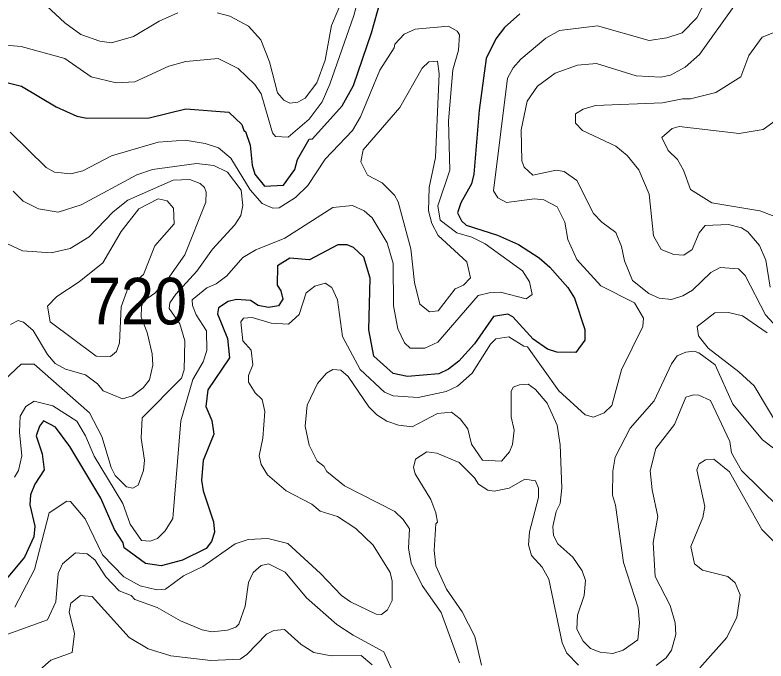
# Model space of a CAD drawing. Extents: x 763.2 to 816.8, y 7896.5 to 7952.7.
# Drawn here: x 775.277 to 777.852, y 7898.239 to 7900.455 of the extents above; entities that cross this region are included whole.
import ezdxf

# ---------------------------------------------------------------- set-up
doc = ezdxf.new("R2010")
doc.units = 0
doc.header["$LTSCALE"] = 0.064
doc.layers.add('1', color=7, linetype='Continuous', lineweight=25)
doc.layers.add('2', color=7, linetype='Continuous', lineweight=13)
doc.layers.add('21', color=7, linetype='Continuous')

msp = doc.modelspace()

# ---------------------------------------------------------------- linework, layer by layer
at = {"layer": '1'}
for points in [[(775.2301, 7900.2279), (775.2989, 7900.211), (775.4186, 7900.1394), (775.4885, 7900.1076), (775.5237, 7900.101), (775.7373, 7900.1018), (775.8624, 7900.1333), (776.0101, 7900.1218), (776.055, 7900.0789), (776.0611, 7900.0588), (776.0675, 7900.0556), (776.0838, 7900.0082), (776.0896, 7899.9396), (776.0991, 7899.9085), (776.1319, 7899.8674), (776.1976, 7899.8714), (776.236, 7899.9249), (776.246, 7899.9593), (776.2859, 7900.029), (776.2974, 7900.0304), (776.3984, 7900.1436), (776.4371, 7900.2135), (776.4996, 7900.3941), (776.5296, 7900.5033)], [(777.0079, 7900.4589), (776.9557, 7900.4118), (776.9257, 7900.3735), (776.8926, 7900.3054), (776.8685, 7900.1284), (776.8501, 7899.9092), (776.8417, 7899.8757), (776.806, 7899.8105), (776.7942, 7899.7766), (776.8076, 7899.7486), (776.8239, 7899.7343), (776.9315, 7899.7), (777.0038, 7899.6672), (777.0737, 7899.6219), (777.1109, 7899.5899), (777.1721, 7899.5205), (777.1954, 7899.4837), (777.231, 7899.3766), (777.2307, 7899.3391), (777.1998, 7899.2974), (777.1345, 7899.2984), (777.1025, 7899.309), (777.053, 7899.343), (776.9834, 7899.4193), (776.9666, 7899.4282), (776.9179, 7899.4204), (776.8528, 7899.3275), (776.7984, 7899.267), (776.7629, 7899.2396), (776.73, 7899.2244), (776.6225, 7899.215), (776.5739, 7899.2249), (776.5075, 7899.2849), (776.4902, 7899.3752), (776.495, 7899.5527), (776.4725, 7899.624), (776.437, 7899.6571), (776.4161, 7899.6666), (776.3834, 7899.6666), (776.2863, 7899.6149), (776.219, 7899.6205), (776.1769, 7899.5947), (776.1762, 7899.5281), (776.1886, 7899.5086), (776.1956, 7899.4802), (776.1809, 7899.4571), (776.1459, 7899.4517), (776.1107, 7899.4582), (776.0847, 7899.4752), (776.0366, 7899.4795), (776.008, 7899.4724), (775.9742, 7899.4506), (775.9712, 7899.4296), (776.0053, 7899.3456), (776.0118, 7899.279), (775.9381, 7899.1688), (775.9317, 7899.1124), (775.9523, 7899.0644), (775.9592, 7899.0172), (775.922, 7898.9272), (775.9166, 7898.8599), (775.9218, 7898.823), (775.9572, 7898.7169), (775.9607, 7898.6808), (775.9505, 7898.6494), (775.9323, 7898.6247), (775.8508, 7898.5855), (775.7785, 7898.5659), (775.7249, 7898.5739), (775.6509, 7898.6278), (775.6481, 7898.6449), (775.6183, 7898.6905), (775.5714, 7898.7974), (775.4647, 7898.9754), (775.4159, 7899.0415), (775.375, 7899.063), (775.3608, 7899.045), (775.3497, 7899.011), (775.3697, 7898.9502), (775.3772, 7898.8944)], [(775.3772, 7898.8944), (775.3444, 7898.846), (775.3298, 7898.8089), (775.3283, 7898.7744), (775.3446, 7898.7016), (775.341, 7898.6652)], [(775.341, 7898.6652), (775.3092, 7898.5952), (775.218, 7898.4869)]]:
    msp.add_lwpolyline(points, dxfattribs=at)
at = {"layer": '2'}
for points in [[(776.4204, 7900.5571), (776.3625, 7900.4192), (776.3406, 7900.3002), (776.3114, 7900.222), (776.2719, 7900.1693), (776.2471, 7900.1563), (776.2188, 7900.1519), (776.1981, 7900.1627), (776.1767, 7900.1881), (776.1495, 7900.2943), (776.1194, 7900.3697), (776.077, 7900.4166), (776.0134, 7900.4507), (775.9698, 7900.462)], [(775.1804, 7900.3572), (775.2979, 7900.3472), (775.448, 7900.3053), (775.5379, 7900.2426), (775.6233, 7900.2223), (775.688, 7900.2261), (775.8049, 7900.2798), (775.8623, 7900.2958), (775.9739, 7900.3059), (776.042, 7900.2711), (776.0993, 7900.217), (776.1205, 7900.185), (776.1596, 7900.0507), (776.1696, 7900.0381), (776.2134, 7900.0358), (776.2851, 7900.0979), (776.3298, 7900.1565), (776.3569, 7900.2174), (776.4388, 7900.4533), (776.4622, 7900.5427)], [(777.6619, 7900.5362), (777.6146, 7900.4448), (777.5641, 7900.3938), (777.5115, 7900.3769), (777.4517, 7900.3672), (777.2747, 7900.4176), (777.1441, 7900.4012), (777.0973, 7900.3754), (777.0117, 7900.3033), (776.9848, 7900.2732), (776.9653, 7900.2384), (776.9175, 7899.852), (776.9324, 7899.828), (776.9618, 7899.8117), (777.0579, 7899.8244), (777.0906, 7899.8208), (777.1357, 7899.7965), (777.1619, 7899.7447), (777.1725, 7899.6843), (777.2035, 7899.6163), (777.2852, 7899.5262), (777.4015, 7899.4682), (777.4315, 7899.4147), (777.4301, 7899.3867), (777.3563, 7899.2379), (777.3231, 7899.1152), (777.2974, 7899.0903), (777.2602, 7899.0755), (777.2322, 7899.0832), (777.1417, 7899.1662), (777.0338, 7899.3163), (777.0211, 7899.3186), (776.9704, 7899.3512), (776.9254, 7899.3439), (776.9076, 7899.3259), (776.8444, 7899.2263), (776.794, 7899.1823), (776.7547, 7899.164), (776.6594, 7899.1426), (776.5734, 7899.1488), (776.5437, 7899.161), (776.4604, 7899.2387), (776.4002, 7899.3523), (776.3831, 7899.4778), (776.3633, 7899.5204), (776.34, 7899.5349), (776.3046, 7899.5252), (776.2749, 7899.5016), (776.2513, 7899.4275), (776.2143, 7899.3946), (776.1558, 7899.3975), (776.09, 7899.4169), (776.0608, 7899.4146), (776.0514, 7899.4023), (776.0578, 7899.3373), (776.0871, 7899.3051), (776.0922, 7899.2551), (776.078, 7899.2183), (776.0778, 7899.196), (776.1009, 7899.1591), (776.1249, 7899.1359), (776.1331, 7899.0949), (776.1271, 7899.0029), (776.1138, 7898.9428), (776.1204, 7898.9133), (776.1424, 7898.8775), (776.2072, 7898.8228), (776.2944, 7898.7776), (776.3236, 7898.7536), (776.3826, 7898.7351), (776.445, 7898.6934), (776.5044, 7898.6369), (776.5632, 7898.5425), (776.5703, 7898.5131), (776.5705, 7898.4466), (776.5539, 7898.4142), (776.5332, 7898.3989), (776.5154, 7898.3997), (776.4275, 7898.4416), (776.3967, 7898.4635), (776.3241, 7898.5394), (776.2121, 7898.6418), (776.1433, 7898.6592), (776.0769, 7898.6559), (776.0319, 7898.6414), (775.9204, 7898.5629), (775.8548, 7898.5314), (775.7924, 7898.4852), (775.7637, 7898.4838)], [(775.8357, 7900.4619), (775.7713, 7900.434), (775.6831, 7900.3814), (775.6082, 7900.359), (775.5681, 7900.3653), (775.5031, 7900.388), (775.4482, 7900.4278), (775.3845, 7900.4864)], [(777.8761, 7899.3982), (777.8501, 7899.4265), (777.7801, 7899.5616), (777.758, 7899.5846), (777.6949, 7899.5893), (777.6629, 7899.5715), (777.6001, 7899.5114), (777.5669, 7899.492), (777.5279, 7899.4788), (777.4858, 7899.4839), (777.4503, 7899.5), (777.3947, 7899.5447), (777.3663, 7899.612), (777.3563, 7899.6613), (777.3373, 7899.7091), (777.2889, 7899.7441), (777.2605, 7899.7742), (777.2028, 7899.8874), (777.1598, 7899.9181), (777.1327, 7899.923), (777.0529, 7899.9055), (777.0226, 7899.9332), (777.0145, 7899.9551), (777.0128, 7900.0611), (777.0334, 7900.1594), (777.0686, 7900.2108), (777.1295, 7900.2552), (777.2051, 7900.283), (777.2702, 7900.2881), (777.4065, 7900.2467), (777.4916, 7900.2421), (777.5243, 7900.2488), (777.575, 7900.2762), (777.6235, 7900.3189), (777.7412, 7900.4841)], [(776.5011, 7899.7591), (776.5533, 7899.6732), (776.5738, 7899.602), (776.5744, 7899.4569), (776.5891, 7899.3781), (776.6127, 7899.3302), (776.6321, 7899.3124), (776.6824, 7899.3119), (776.7267, 7899.3332), (776.8652, 7899.4926), (776.9026, 7899.5023), (776.9413, 7899.504), (777.0293, 7899.4813), (777.0503, 7899.4958), (777.0409, 7899.5395), (777.0172, 7899.5777), (776.8888, 7899.6704), (776.8431, 7899.6926), (776.7923, 7899.7073), (776.735, 7899.7513), (776.727, 7899.8005), (776.7678, 7899.9222), (776.7629, 7900.0922), (776.7778, 7900.2666), (776.7971, 7900.3343), (776.8007, 7900.3873), (776.793, 7900.3989), (776.7636, 7900.4162), (776.6489, 7900.4061), (776.6118, 7900.3887), (776.5791, 7900.355), (776.5767, 7900.3421), (776.5273, 7900.2652), (776.4621, 7900.1056), (776.4337, 7900.0591), (776.3403, 7899.9602), (776.2812, 7899.8704), (776.239, 7899.8286), (776.1823, 7899.7934), (776.1614, 7899.7922), (776.1239, 7899.8083), (776.0832, 7899.8555), (776.0173, 7899.9638), (775.9748, 7899.999), (775.929, 7900.0136), (775.8606, 7900.025), (775.768, 7900.0183), (775.6077, 7899.9723), (775.5096, 7899.9203), (775.4688, 7899.9102), (775.4126, 7899.9162), (775.3833, 7899.9315), (775.2608, 7900.053)], [(777.8822, 7900.3963), (777.8389, 7900.3793), (777.7935, 7900.316), (777.766, 7900.2429), (777.6804, 7900.189), (777.5933, 7900.1672), (777.5651, 7900.1677), (777.4968, 7900.1533), (777.2668, 7900.1448), (777.2254, 7900.1321), (777.1991, 7900.1154), (777.1989, 7900.084), (777.2227, 7900.0586), (777.3371, 7900.0049), (777.3759, 7899.9725), (777.4161, 7899.9235), (777.4513, 7899.8401), (777.4658, 7899.697), (777.4928, 7899.6507), (777.536, 7899.6335), (777.5706, 7899.6313), (777.599, 7899.6507), (777.6225, 7899.7079), (777.6437, 7899.7325), (777.7236, 7899.7358), (777.7681, 7899.7254), (777.7901, 7899.711), (777.8298, 7899.6644), (777.8508, 7899.6137), (777.8659, 7899.5216)], [(777.8823, 7899.7635), (777.8302, 7899.7833), (777.6666, 7899.811), (777.5926, 7899.8564), (777.569, 7899.9229), (777.5483, 7899.9591), (777.5168, 7899.9896), (777.4948, 7900.0352), (777.5304, 7900.066), (777.5542, 7900.0727), (777.7598, 7900.0481), (777.8419, 7900.0627), (777.8882, 7900.0953)], [(775.2708, 7899.8505), (775.305, 7899.8165), (775.3579, 7899.7901), (775.4249, 7899.7788), (775.5034, 7899.8032), (775.6943, 7899.9072), (775.7478, 7899.9255), (775.8987, 7899.946), (775.9587, 7899.9381), (776.0056, 7899.9161), (776.052, 7899.8544), (776.0576, 7899.8018), (776.0512, 7899.7671), (776.0308, 7899.7354), (775.9544, 7899.652), (775.9001, 7899.5765), (775.8279, 7899.4975), (775.8082, 7899.4679), (775.8051, 7899.4485), (775.8423, 7899.3958), (775.8588, 7899.3372), (775.857, 7899.2375), (775.8476, 7899.2088), (775.713, 7899.0727), (775.7095, 7899.0038), (775.7208, 7898.9284), (775.7174, 7898.8921), (775.6992, 7898.8419), (775.6809, 7898.8323), (775.6591, 7898.8368), (775.62, 7898.875), (775.6061, 7898.9027), (775.5747, 7899.0088), (775.5319, 7899.0899), (775.3422, 7899.2567), (775.298, 7899.2576), (775.22, 7899.1852)], [(775.2617, 7899.3931), (775.2883, 7899.407), (775.3061, 7899.4015), (775.3393, 7899.3729), (775.3878, 7899.2899), (775.4149, 7899.2599), (775.4502, 7899.24), (775.519, 7899.2207), (775.5601, 7899.1898), (775.5797, 7899.1663), (775.6458, 7899.138), (775.6801, 7899.1484), (775.7169, 7899.1765), (775.7376, 7899.2037), (775.7493, 7899.2544), (775.7476, 7899.2927), (775.7296, 7899.3656), (775.7099, 7899.419), (775.7101, 7899.4553), (775.719, 7899.474), (775.7567, 7899.5003), (775.7999, 7899.5471), (775.8597, 7899.6321), (775.9312, 7899.8132), (775.9328, 7899.8468), (775.9264, 7899.8632), (775.9121, 7899.8767), (775.8764, 7899.8903), (775.8187, 7899.8886), (775.6635, 7899.8196), (775.6136, 7899.7798), (775.5308, 7899.694), (775.4661, 7899.6539), (775.4005, 7899.6389), (775.3021, 7899.6464), (775.1968, 7899.6948)], [(776.1027, 7899.6496), (776.2025, 7899.6899), (776.3668, 7899.7949), (776.4339, 7899.8014), (776.4746, 7899.7837), (776.5011, 7899.7591)], [(775.2755, 7898.8701), (775.2887, 7898.8928), (775.3002, 7898.9427), (775.2921, 7899.0236), (775.2946, 7899.0785), (775.3139, 7899.1119), (775.3432, 7899.1308), (775.4071, 7899.1146), (775.489, 7899.0619), (775.5184, 7899.0118), (775.5488, 7898.9414), (775.6462, 7898.7791), (775.6717, 7898.7088), (775.7107, 7898.6527), (775.74, 7898.6497), (775.7659, 7898.6592), (775.7914, 7898.686), (775.818, 7898.7282), (775.8458, 7899.063), (775.887, 7899.205), (775.922, 7899.2656), (775.9346, 7899.3043), (775.9331, 7899.3715), (775.8978, 7899.4267), (775.8851, 7899.4585), (775.8842, 7899.4781), (775.9349, 7899.5187), (775.967, 7899.5323), (776.0034, 7899.56), (776.0585, 7899.6228), (776.1027, 7899.6496)], [(777.8954, 7899.0407), (777.8109, 7899.1824), (777.7586, 7899.2312), (777.6537, 7899.3119), (777.6199, 7899.355), (777.6161, 7899.3866), (777.676, 7899.4333), (777.7237, 7899.435), (777.7715, 7899.4226), (777.8557, 7899.3644)], [(776.5798, 7898.7517), (776.407, 7898.8398), (776.3457, 7898.8896), (776.3354, 7898.9072), (776.3127, 7898.9244), (776.2859, 7898.9796), (776.2716, 7899.0446), (776.2792, 7899.1164), (776.3139, 7899.1912), (776.3455, 7899.2262), (776.3663, 7899.239), (776.3941, 7899.2362), (776.4194, 7899.2148), (776.4905, 7899.111), (776.5176, 7899.084), (776.5516, 7899.0618), (776.5917, 7899.0486), (776.6385, 7899.0424), (776.7258, 7899.0885), (776.7735, 7899.0921), (776.8037, 7899.0701), (776.8299, 7899.0355), (776.8416, 7898.9826), (776.8798, 7898.9275), (776.9455, 7898.9245), (776.9727, 7898.9562), (776.9824, 7898.9813), (776.9881, 7899.0314), (776.9783, 7899.0769), (776.9784, 7899.164), (776.9848, 7899.178), (777.0067, 7899.1866), (777.0361, 7899.1885), (777.062, 7899.1704), (777.1021, 7899.124), (777.1357, 7899.0479), (777.146, 7898.9802), (777.1524, 7898.8336), (777.1459, 7898.7792), (777.1325, 7898.7517), (777.1215, 7898.7002), (777.123, 7898.6699), (777.138, 7898.6414), (777.1899, 7898.595), (777.221, 7898.5482), (777.2327, 7898.5154), (777.2285, 7898.4644), (777.2052, 7898.3964), (777.2035, 7898.3479), (777.2252, 7898.3072), (777.2497, 7898.2824), (777.2836, 7898.269), (777.3266, 7898.265), (777.3625, 7898.2765), (777.4127, 7898.3119), (777.4187, 7898.3703), (777.4138, 7898.4221), (777.3629, 7898.5766), (777.3364, 7898.7738), (777.325, 7898.808), (777.3267, 7898.8901), (777.3348, 7898.9382), (777.3858, 7899.0374), (777.4683, 7899.1317), (777.5276, 7899.2582), (777.5475, 7899.2862), (777.5765, 7899.2986), (777.6058, 7899.3017), (777.6214, 7899.2963), (777.6778, 7899.2545), (777.7379, 7899.1205), (777.8396, 7898.9978), (777.9443, 7898.9189)], [(777.6611, 7899.1329), (777.6217, 7899.1507), (777.6035, 7899.1523), (777.5774, 7899.1444), (777.5382, 7899.05), (777.4744, 7898.9677)], [(777.8953, 7898.7663), (777.7676, 7898.8924), (777.7341, 7898.9526), (777.7274, 7898.9917), (777.6611, 7899.1329)], [(777.209, 7898.2252), (777.1694, 7898.2663), (777.1528, 7898.3014), (777.1068, 7898.5199), (777.0846, 7898.5614), (777.0476, 7898.6016), (777.0381, 7898.638), (777.0407, 7898.6824), (777.0716, 7898.8001), (777.0719, 7898.8325), (777.061, 7898.8572), (777.025, 7898.863), (776.9707, 7898.8317), (776.9197, 7898.8222), (776.8976, 7898.8252), (776.8658, 7898.846), (776.8524, 7898.8673), (776.7994, 7898.9198), (776.7232, 7898.9515), (776.6895, 7898.9564), (776.6506, 7898.9312), (776.643, 7898.9033), (776.6489, 7898.8806), (776.7028, 7898.7928), (776.7203, 7898.7474), (776.7251, 7898.7149), (776.7202, 7898.7092), (776.7136, 7898.6183), (776.7199, 7898.5654), (776.7561, 7898.486), (776.8105, 7898.4079), (776.8535, 7898.3235), (776.8763, 7898.2248)], [(777.4744, 7898.9677), (777.4549, 7898.8909), (777.4615, 7898.8263), (777.481, 7898.735), (777.4647, 7898.6455), (777.4713, 7898.5287), (777.5235, 7898.4299), (777.5401, 7898.3701), (777.5432, 7898.3301), (777.5284, 7898.2761), (777.5095, 7898.2495), (777.4751, 7898.2242)], [(777.6252, 7898.2152), (777.7173, 7898.3203), (777.752, 7898.3892), (777.7637, 7898.4666), (777.7463, 7898.5068), (777.7208, 7898.5293), (777.634, 7898.5509), (777.6067, 7898.5719), (777.5946, 7898.6324), (777.6352, 7898.7313), (777.642, 7898.7696), (777.6143, 7898.8948), (777.6223, 7898.9151), (777.6443, 7898.9294), (777.6726, 7898.932), (777.7269, 7898.8884), (777.8377, 7898.69), (777.8809, 7898.6466)], [(775.4673, 7898.7865), (775.4542, 7898.7876), (775.3936, 7898.7469), (775.3435, 7898.5525), (775.2765, 7898.4239)], [(775.7637, 7898.4838), (775.7063, 7898.4967), (775.6504, 7898.528), (775.5766, 7898.6032), (775.5179, 7898.7265), (775.4673, 7898.7865)], [(776.6726, 7898.4984), (776.6356, 7898.575), (776.6266, 7898.6259), (776.6295, 7898.6925), (776.6083, 7898.725), (776.5798, 7898.7517)], [(775.1854, 7898.307), (775.3882, 7898.3799), (775.4169, 7898.4425), (775.4244, 7898.5393), (775.4398, 7898.5723), (775.484, 7898.6107), (775.524, 7898.6071), (775.5511, 7898.5858), (775.588, 7898.5278), (775.6339, 7898.4794), (775.6747, 7898.4636), (775.6882, 7898.45), (775.7647, 7898.4229), (775.8442, 7898.3768), (775.9192, 7898.3457), (775.9521, 7898.3391), (776.0051, 7898.3447), (776.0336, 7898.3548), (776.0447, 7898.3658), (776.0665, 7898.4277), (776.0779, 7898.5082), (776.0935, 7898.543), (776.1204, 7898.5672), (776.1466, 7898.5721), (776.2029, 7898.5439), (776.2765, 7898.4557), (776.3805, 7898.3646), (776.436, 7898.3275), (776.5412, 7898.2707), (776.5716, 7898.2047)], [(776.8012, 7898.2333), (776.7383, 7898.4056), (776.6726, 7898.4984)], [(776.5016, 7898.226), (776.4638, 7898.2585), (776.3604, 7898.2568), (776.3018, 7898.2681), (776.2586, 7898.2953), (776.2006, 7898.3469), (776.1647, 7898.3435), (776.1391, 7898.3316), (776.0721, 7898.2611), (776.0489, 7898.2457), (775.948, 7898.2404), (775.8113, 7898.2568), (775.7339, 7898.2809), (775.668, 7898.3201), (775.5417, 7898.4603), (775.5013, 7898.4637), (775.468, 7898.4372), (775.463, 7898.4075), (775.481, 7898.334), (775.4727, 7898.2688), (775.4, 7898.2415), (775.3334, 7898.1843)]]:
    msp.add_lwpolyline(points, dxfattribs=at)
for points in [[(776.4623, 7899.9518), (776.4708, 7899.9921), (776.5967, 7900.1373), (776.6724, 7900.2727), (776.6963, 7900.2947), (776.725, 7900.2969), (776.7316, 7900.2528), (776.7183, 7899.9661), (776.6969, 7899.8633), (776.6944, 7899.783), (776.706, 7899.7393), (776.7277, 7899.6983), (776.8265, 7899.6079), (776.839, 7899.5536), (776.8144, 7899.5278), (776.7865, 7899.516), (776.7282, 7899.4403), (776.6979, 7899.4369), (776.6654, 7899.4636), (776.6462, 7899.5377), (776.6345, 7899.6527), (776.5911, 7899.8145), (776.5784, 7899.8365), (776.5357, 7899.8792), (776.4853, 7899.9054)], [(775.8226, 7899.7383), (775.8199, 7899.7919), (775.799, 7899.8172), (775.7682, 7899.8242), (775.7019, 7899.7901), (775.6414, 7899.7126), (775.5785, 7899.6049), (775.4964, 7899.5391), (775.4203, 7899.4893), (775.3879, 7899.4562), (775.3975, 7899.4023), (775.5552, 7899.2844), (775.6049, 7899.2837), (775.625, 7899.3009), (775.6347, 7899.3308), (775.6405, 7899.4541), (775.6655, 7899.5207), (775.717, 7899.5645), (775.7564, 7899.6634)]]:
    msp.add_lwpolyline(points, close=True, dxfattribs=at)

# ---------------------------------------------------------------- texts
at = {"layer": '21', "width": 0.95}
msp.add_text('720', height=0.16, dxfattribs=at).set_placement((775.5272, 7899.3934))

doc.saveas('drawing.dxf')
